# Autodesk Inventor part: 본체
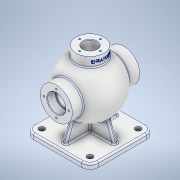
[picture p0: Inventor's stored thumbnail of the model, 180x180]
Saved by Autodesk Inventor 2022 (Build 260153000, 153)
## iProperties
Created: 2024-04
Part Number: 본체
Material: 알루미늄 6061
Document SubType Name: Modeling
Designer: Admin
Density: 2.7 g/cm^3
Appearance: 알루미늄 - 평지
Mass: 1526.84 g
Surface Area: 1174.29 cm^2
Volume: 565.495 cm^3
Author: Admin
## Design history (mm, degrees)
sketch "스케치1"
  geometry: L1 (0, 92.864)-(0, -99.249); A1 r 54 centre (0, 0) between (0, -54) and (0, 54); 1 further point
  constraints: 3 point on line, 2 end point, 2 point on circle, 1 centre point, 1 coincident, 1 vertical
  dimensions: "d0" = 108 diameter of A1
revolve "회전1" sketch "스케치1" stored, may be unused: angle "d1" = 90 deg
node "작업 평면1"
sketch "스케치3"
  geometry: L1 (-62.5, 62.5)-(62.5, 62.5); L2 (62.5, 62.5)-(62.5, -62.5); L3 (62.5, -62.5)-(-62.5, -62.5); L4 (-62.5, -62.5)-(-62.5, 62.5); L5 (-62.5, 62.5)-(62.5, -62.5); L6 (62.5, 62.5)-(-62.5, -62.5); 1 further point
  constraints: 12 end point, 2 midpoint, 2 parallel, 1 horizontal, 1 perpendicular
  dimensions: "d3" = 125 distance of L2.end L3.end; "d4" = 125 distance of L1.end L2.end
extrude "돌출1" join sketch "스케치3" distance "d5" = 10; taper "d6" = 0 deg
sketch "스케치4"
  geometry: L1 (-75, -62.5)-(-75, 62.5) reference; L2 (-75, 50.5)-(0, 23.202); L3 (0, 23.202)-(0, -23.202); L4 (0, -23.202)-(-75, -50.5); L5 (-75, 50.5)-(-75, -50.5); L6 (-85, 62.5)-(-75, 62.5) reference; L7 (-112.8, 0)-(81.8, 0) reference; 1 further point
  constraints: 8 end point, 2 parallel, 2 point on line, 2 symmetric about line, 1 midpoint
  dimensions: "d7" = 12 distance from line of L6 L2.start; "d8" = 20 deg angle of L2 L6
extrude "돌출2" join sketch "스케치4" stored distance "d9" = 8; taper "d10" = 0 deg
sketch "스케치5"
  geometry: L1 (-62.5, -75)-(62.5, -75) reference; L2 (50.5, -75)-(23.202, 0); L3 (23.202, 0)-(-23.202, 0); L4 (-23.202, 0)-(-50.5, -75); L5 (50.5, -75)-(-50.5, -75); L6 (62.5, -85)-(62.5, -75) reference; L7 (0, -112.8)-(0, 81.8) reference; 1 further point
  constraints: 8 end point, 2 horizontal, 2 point on line, 2 symmetric about line, 1 midpoint
  dimensions: "d11" = 12 distance of L1.end L2.start; "d12" = 20 deg angle of L6 L2
extrude "돌출3" join sketch "스케치5" stored distance "d13" = 8; taper "d14" = 0 deg
node "작업 평면2"
sketch "스케치6"
  geometry: C1 r 27 at (0, 0); 1 further point
  constraints: 1 centre point, 1 coincident
  dimensions: "d16" = 54 diameter of C1
extrude "돌출4" join sketch "스케치6" stored distance "d17" = 8; taper "d18" = 0 deg
node "작업 평면3"
sketch "스케치7"
  geometry: C1 r 31 at (0, 0); 1 further point
  constraints: 1 centre point, 1 coincident
  dimensions: "d20" = 62 diameter of C1
extrude "돌출5" join sketch "스케치7" distance "d21" = 130; taper "d22" = 0 deg
sketch "스케치8"
  geometry: L1 (0, 137.901)-(0, -191.245); L2 (-115, 0)-(95, 0) reference; L3 (31, 65)-(-31, 65) reference; L4 (0, 65)-(17.5, 65); L5 (17.5, 65)-(17.5, 49); L6 (17.5, 49)-(0, 49); L7 (0, 49)-(0, 65); L8 (0, 49)-(15, 49); L9 (15, 49)-(15, 41.364); L10 (15, 41.364)-(0, 41.364); L11 (0, 41.364)-(0, 49); L12 (31, -65)-(-31, -65) reference; L13 (0, -65)-(17.5, -65); L14 (17.5, -65)-(17.5, -49); L15 (17.5, -49)-(0, -49); L16 (0, -49)-(0, -65); L17 (0, -49)-(15, -49); L18 (15, -49)-(15, -41.364); L19 (15, -41.364)-(0, -41.364); L20 (0, -41.364)-(0, -49); A1 r 44 centre (0, 0) between (15, -41.364) and (15, 41.364); 7 further points
  constraints: 34 end point, 8 parallel, 4 horizontal, 4 perpendicular, 3 point on line, 2 midpoint, 2 point on circle, 1 centre point, 1 coincident, 1 vertical
  dimensions: "d23" = 44 radius of A1; "d24" = 16 distance of L4.end L5.end; "d25" = 16 distance of L13.end L14.end; "d26" = 35 diameter of L5 L1; "d27" = 30 diameter of L9 L1
revolve "회전2" sketch "스케치8" stored, may be unused: angle "d28" = 90 deg
sketch "스케치9"
  geometry: C1 r 13 at (0, 0); C2 r 27 at (0, 0) reference; 1 further point
  constraints: 1 centre point, 1 concentric
  dimensions: "d29" = 26 diameter of C1
extrude "돌출6" cut sketch "스케치9" stored distance "d30" = 130; taper "d31" = 0 deg
sketch "스케치10" dims "d32" = 48
  geometry: L1 (-87.5, 0)-(87.5, 0) reference; L2 (0, -115)-(0, 95) reference; C1 r 31 at (0, 0) reference; 3 further points
  constraints: 1 point on line, 1 vertical alignment, 3 other
hole "구멍1" sketch "스케치10" at (0, 24) diameter "d33" = 3.242; stored, may be unused: countersink angle "d37" = 90 deg, drill point angle "d39" = 118 deg; dims "d34" = 12, "d35" = 4, "d36" = 2, "d38" = 15
sketch "스케치11" dims "d43" = 40
  geometry: L1 (0, 91)-(0, -91) reference; C1 r 27 at (0, 0) reference; 3 further points
  constraints: 1 point on line, 1 vertical alignment, 3 other
hole "구멍2" sketch "스케치11" at (0, -20) diameter "d44" = 3.242; stored, may be unused: countersink angle "d48" = 90 deg, drill point angle "d50" = 118 deg; dims "d45" = 9, "d46" = 4, "d47" = 2, "d49" = 11
node "작업 평면4"
sketch "스케치12"
  geometry: L1 (-115, 0)-(95, 0) reference; L2 (65, 27)-(65, -27) reference; 2 further points
  constraints: 1 point on line, 1 other
  dimensions: "d55" = 9 distance from line of L2 point (56, 0)
feature "엠보싱1" sketch "스케치12" dims "d0" = 108, "d56" = 0.5, "d57" = 0
fillet "모깎기1" dims "d58" = 0.6
fillet "모깎기2" dims "d59" = 0.6
chamfer "모따기1" distance "d60" = 1; stored, may be unused: second distance "d61" = 2, angle "d62" = 45 deg
chamfer "모따기2" distance "d63" = 1; stored, may be unused: second distance "d64" = 2, angle "d65" = 45 deg
fillet "모깎기3" dims "d66" = 3
fillet "모깎기4" dims "d67" = 3
fillet "모깎기5" dims "d68" = 3
fillet "모깎기6" dims "d69" = 16
sketch "스케치13"
  geometry: L1 (-62.5, 46.5)-(-62.5, -46.5) reference; L2 (-46.5, -62.5)-(46.5, -62.5) reference; L3 (62.5, -46.5)-(62.5, 46.5) reference; L4 (46.5, 62.5)-(-46.5, 62.5) reference; L5 (-1, -52.601)-(1, -52.601) reference; L6 (-7, -7)-(-7, -46.216) reference; L7 (-46.216, -7)-(-7, -7) reference; L8 (-52.601, 1)-(-52.601, -1) reference; L9 (-7, 7)-(-46.216, 7) reference; L10 (-7, 46.216)-(-7, 7) reference; L11 (1, 52.601)-(-1, 52.601) reference; L12 (7, 7)-(7, 46.216) reference; L13 (46.216, 7)-(7, 7) reference; L14 (52.601, -1)-(52.601, 1) reference; L15 (7, -7)-(46.216, -7) reference; L16 (7, -46.216)-(7, -7) reference; C1 r 5.5 at (-46.5, -46.5); C2 r 5.5 at (46.5, -46.5); C3 r 5.5 at (-46.5, 46.5); C4 r 5.5 at (46.5, 46.5); A1 r 16 centre (-46.5, 46.5) between (-46.5, 62.5) and (-62.5, 46.5) reference; A2 r 16 centre (-46.5, -46.5) between (-62.5, -46.5) and (-46.5, -62.5) reference; A3 r 16 centre (46.5, -46.5) between (46.5, -62.5) and (62.5, -46.5) reference; A4 r 16 centre (46.5, 46.5) between (62.5, 46.5) and (46.5, 62.5) reference; A5 r 16 centre (-46.5, 46.5) between (-46.5, 62.5) and (-62.5, 46.5) reference; A6 r 16 centre (-46.5, -46.5) between (-62.5, -46.5) and (-46.5, -62.5) reference; 9 further points; 8 other entities
  constraints: 4 centre point, 4 concentric, 8 other
  dimensions: "d70" = 11 diameter of C1; "d71" = 11 diameter of C2; "d72" = 11 diameter of C3; "d73" = 11 diameter of C4
extrude "돌출7" cut sketch "스케치13" extent not by distance; stored distance "d74" = 0; taper "d75" = 0 deg
fillet "모깎기7" dims "d76" = 3
chamfer "모따기3" distance "d77" = 1; stored, may be unused: second distance "d78" = 2, angle "d79" = 45 deg
node "솔리드1"
pattern_circular "원형 패턴1" dims angle "d41" = 360 deg
mirror "미러1"
pattern_circular "원형 패턴2" dims angle "d52" = 360 deg
node "투영된 루프1"
feature "A9D066F2-1C7D-4E18-AEED-F7BC21143FA4" dims "d33" = 3.242, "d34" = 12, "d35" = 4, "d36" = 2, "d37" = 90 deg, "d38" = 15, "d39" = 118 deg
other parameters: "d2" = -85, "d19" = -65, "d54" = 243
